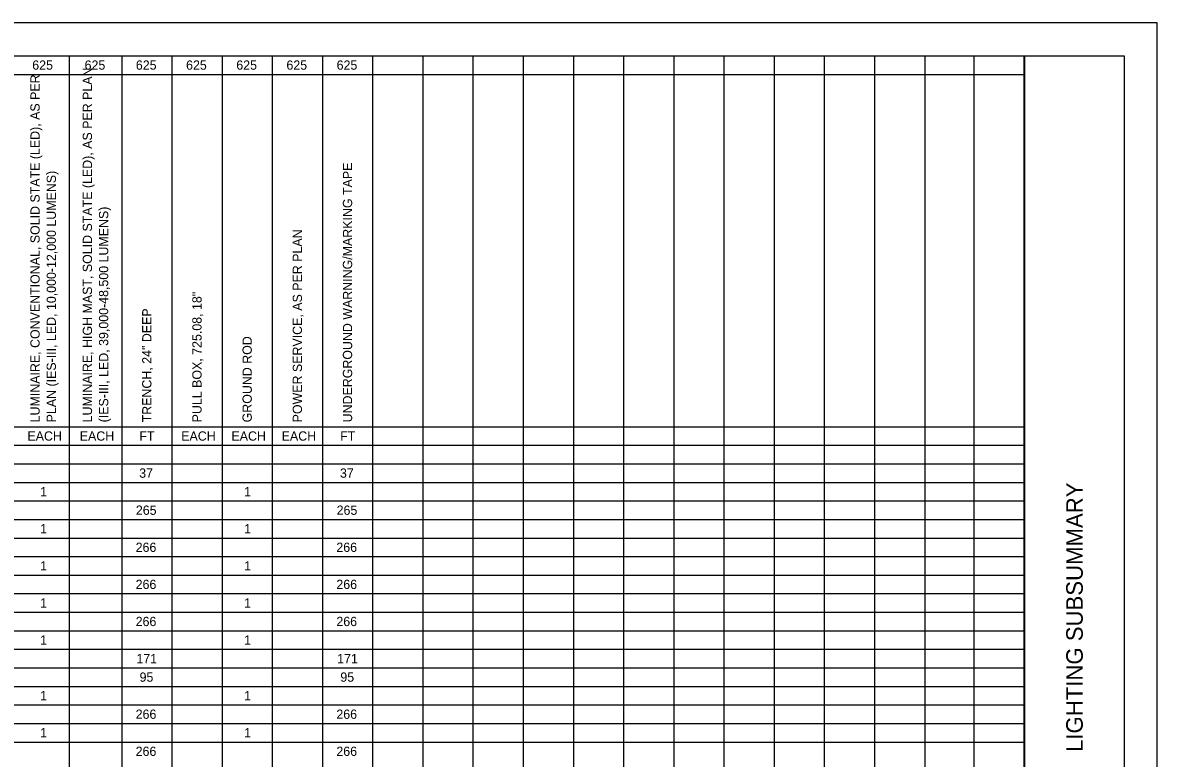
# Model space of a CAD drawing. Extents: x 0 to 34, y 0 to 22.
# Drawn here: x 16.87 to 34, y 10.89 to 22 of the extents above; entities that cross this region are included whole.
import ezdxf

# ---------------------------------------------------------------- set-up
doc = ezdxf.new("R2010")
doc.units = 0
for name, color, linetype in [('SH_Border', 7, 'Continuous'), ('SH_Cut_Line', 7, 'Continuous'), ('SH_Data', 7, 'Continuous'), ('SH_Text', 7, 'Continuous')]:
    doc.layers.add(name, color=color, linetype=linetype)

msp = doc.modelspace()

# ---------------------------------------------------------------- linework, layer by layer
at = {"layer": 'SH_Border'}
msp.add_line((32, 0.5), (32, 21.5), dxfattribs=at)
msp.add_lwpolyline([(1.5, 21.5), (33.5, 21.5), (33.5, 0.5), (1.5, 0.5)], close=True, dxfattribs=at)
at = {"layer": 'SH_Cut_Line'}
msp.add_lwpolyline([(0, 0), (34, 0), (34, 22), (0, 22)], close=True, dxfattribs=at)
at = {"layer": 'SH_Text'}
for p, q in [((1.5, 21.5), (31.987, 21.5)), ((17.575, 21.5), (17.575, 0.5)), ((18.366, 21.5), (18.366, 0.5)), ((19.124, 21.5), (19.124, 0.5)), ((19.881, 21.5), (19.881, 0.5)), ((20.639, 21.5), (20.639, 0.5)), ((21.396, 21.5), (21.396, 0.5)), ((22.154, 21.5), (22.154, 0.5)), ((22.912, 21.5), (22.912, 0.5)), ((23.669, 21.5), (23.669, 0.5)), ((24.427, 21.5), (24.427, 0.5)), ((25.185, 21.5), (25.185, 0.5)), ((25.942, 21.5), (25.942, 0.5)), ((26.7, 21.5), (26.7, 0.5)), ((27.458, 21.5), (27.458, 0.5)), ((28.215, 21.5), (28.215, 0.5)), ((28.973, 21.5), (28.973, 0.5)), ((29.731, 21.5), (29.731, 0.5)), ((30.488, 21.5), (30.488, 0.5)), ((31.229, 21.5), (31.229, 0.5)), ((31.987, 21.5), (31.987, 0.5)), ((8.451, 21.22), (31.987, 21.22)), ((8.451, 15.9), (31.987, 15.9)), ((1.5, 15.62), (31.987, 15.62)), ((1.5, 15.34), (31.987, 15.34)), ((1.5, 15.06), (31.987, 15.06)), ((1.5, 14.78), (31.987, 14.78)), ((1.5, 14.5), (31.987, 14.5)), ((1.5, 14.22), (31.987, 14.22)), ((1.5, 13.94), (31.987, 13.94)), ((1.5, 13.66), (31.987, 13.66)), ((1.5, 13.38), (31.987, 13.38)), ((1.5, 13.1), (31.987, 13.1)), ((1.5, 12.82), (31.987, 12.82)), ((1.5, 12.54), (31.987, 12.54)), ((1.5, 12.26), (31.987, 12.26)), ((1.5, 11.98), (31.987, 11.98)), ((1.5, 11.7), (31.987, 11.7)), ((1.5, 11.42), (31.987, 11.42)), ((1.5, 11.14), (31.987, 11.14))]:
    msp.add_line(p, q, dxfattribs=at)

# ---------------------------------------------------------------- texts
at = {"layer": 'SH_Data'}
msp.add_text('LIGHTING SUBSUMMARY', height=0.25, rotation=90, dxfattribs=at).set_placement((32.875, 10.99))
at = {"layer": 'SH_Text'}
for s, p in [('625', (17.016, 21.29)), ('625', (17.806, 21.29)), ('625', (18.58, 21.29)), ('625', (19.338, 21.29)), ('625', (20.096, 21.29)), ('625', (20.853, 21.29)), ('625', (21.611, 21.29)), ('EACH', (16.943, 15.69)), ('EACH', (17.733, 15.69)), ('FT', (18.633, 15.69)), ('EACH', (19.265, 15.69)), ('EACH', (20.023, 15.69)), ('EACH', (20.781, 15.69)), ('FT', (21.664, 15.69)), ('37', (18.63, 15.13)), ('37', (21.661, 15.13)), ('1', (17.135, 14.85)), ('1', (20.215, 14.85)), ('265', (18.58, 14.57)), ('265', (21.611, 14.57)), ('1', (17.135, 14.29)), ('1', (20.215, 14.29)), ('266', (18.577, 14.01)), ('266', (21.607, 14.01)), ('1', (17.135, 13.73)), ('1', (20.215, 13.73)), ('266', (18.577, 13.45)), ('266', (21.607, 13.45)), ('1', (17.135, 13.17)), ('1', (20.215, 13.17)), ('266', (18.577, 12.89)), ('266', (21.607, 12.89)), ('1', (17.135, 12.61)), ('1', (20.215, 12.61)), ('171', (18.588, 12.33)), ('171', (21.619, 12.33)), ('95', (18.636, 12.05)), ('95', (21.667, 12.05)), ('1', (17.135, 11.77)), ('1', (20.215, 11.77)), ('266', (18.577, 11.49)), ('266', (21.607, 11.49)), ('1', (17.135, 11.21)), ('1', (20.215, 11.21)), ('266', (18.577, 10.93)), ('266', (21.607, 10.93))]:
    msp.add_text(s, height=0.14, dxfattribs=at).set_placement(p)
for s, p in [('LUMINAIRE, HIGH MAST, SOLID STATE (LED), AS PER PLAN ', (17.918, 15.966)), ('LUMINAIRE, CONVENTIONAL, SOLID STATE (LED), AS PER ', (17.128, 15.966)), ('UNDERGROUND WARNING/MARKING TAPE', (21.845, 15.966)), ('PLAN (IES-III, LED, 10,000-12,000 LUMENS)', (17.373, 15.966)), ('(IES-III, LED, 39,000-48,500 LUMENS)', (18.163, 15.966)), ('POWER SERVICE, AS PER PLAN', (21.088, 15.966)), ('PULL BOX, 725.08, 18"', (19.572, 15.966)), ('TRENCH, 24" DEEP', (18.815, 15.966)), ('GROUND ROD', (20.33, 15.966))]:
    msp.add_text(s, height=0.14, rotation=90, dxfattribs=at).set_placement(p)

doc.saveas('drawing.dxf')
